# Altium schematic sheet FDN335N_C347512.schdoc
size 127 x 101 mm
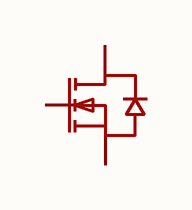
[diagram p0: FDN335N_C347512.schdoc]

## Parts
Q?  fdn335n(umw)  [SOT-23-3_L2.9-W1.3-P1.90-LS2.4-BR]  (value not drawn)

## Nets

Not connected (* = marked no-connect by the designer): Q? 1(G) 2(S) 3(D)

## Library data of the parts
Q? = fdn335n(umw): 数量:1个N沟道;漏源电压(Vdss):20V;连续漏极电流(Id):1.7A;导通电阻(RDS(on)):55mΩ@4.5V;耗散功率(Pd):1W;阈值电压(Vgs(th)):1.5V;; Manufacturer: UMW(友台半导体); Symbol: FDN335N_C347512; AddInBom: yes; ModelId: c62791f0466c4ae2a892c056b845b0ca; ModelName: SOT-23-3P_L2.9-W1.3-H1.0-LS2.4-P0.95; ModelTransform: 98.425,114.173,0,180,0,0,0.0005,-0.0005,0; Number: 1个N沟道; Drain to Source Voltage: 20V; Current - Continuous Drain(Id): 1.7A; Pd - Power Dissipation: 1W; Gate Threshold Voltage (Vgs(th)): 1.5V; Gate Charge(Qg): 3.5nC@4.5V; Input Capacitance(Ciss): 310pF; Reverse Transfer Capacitance (Crss@Vds): 40pF; Type: N沟道; Output Capacitance(Coss): 80pF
